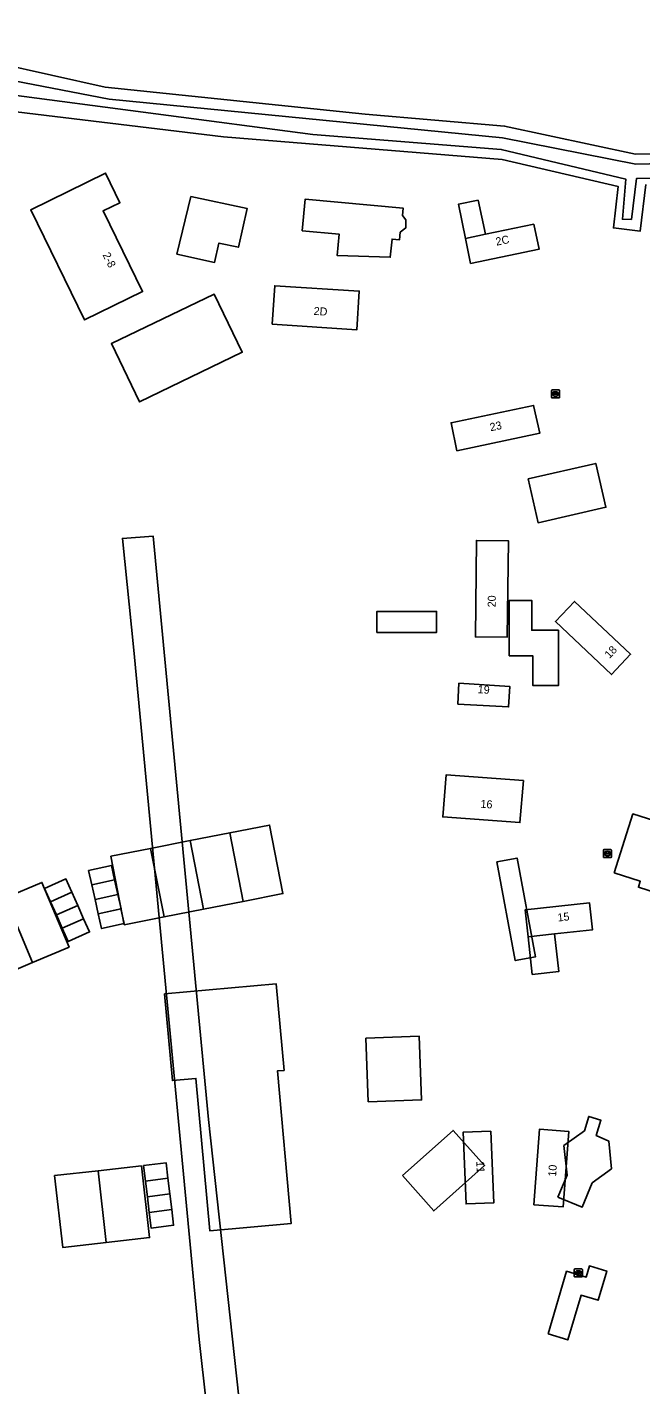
# Model space of a CAD drawing. Extents: x 159451 to 160664, y 388402 to 389723.
# Drawn here: x 160017.1 to 160093.8, y 389378.7 to 389548.3 of the extents above; entities that cross this region are included whole.
import ezdxf

# ---------------------------------------------------------------- set-up
doc = ezdxf.new("R2010")
doc.units = 0
for name, color, linetype in [('IMGEO_Groenvoorziening', 7, 'Continuous'), ('IMGEO_Oever', 7, 'Continuous'), ('IMGEO_Pand', 7, 'Continuous'), ('IMGEO_Pand_nummerreeks', 7, 'Continuous'), ('IMGEO_Pand_overbouw', 7, 'Continuous'), ('IMGEO_Pand_vergunning_verleend', 7, 'Continuous'), ('IMGEO_Rioolput', 7, 'Continuous'), ('IMGEO_Voetpad_open', 7, 'Continuous'), ('IMGEO_Waterloop', 7, 'Continuous')]:
    doc.layers.add(name, color=color, linetype=linetype)

msp = doc.modelspace()

# ---------------------------------------------------------------- linework, layer by layer
at = {"layer": 'IMGEO_Groenvoorziening'}
for points in [[(159864.26, 389539.27), (159877.37, 389542.72), (159910.67, 389547.35), (159921.89, 389548.25), (159950.46, 389547.42), (159979.98, 389545.51), (159991.18, 389543.87), (160013.37, 389543.74), (160026.85, 389540.77), (160059.3, 389537.37), (160076.74, 389535.9), (160093.1, 389532.4), (160106.88, 389532.52)], [(160094.37, 389528.6), (160093.68, 389522.77), (160090.33, 389523.17), (160090.94, 389528.33), (160076.45, 389531.72), (160041.63, 389534.55), (160012.22, 389538.08), (159935.54, 389544.19), (159921.34, 389544.14), (159894.12, 389541.21), (159881.2, 389539.62), (159858.79, 389532.6), (159882.61, 389518.89), (159882.88, 389518.48), (159883.08, 389518.04), (159883.14, 389517.69), (159883.16, 389517.57), (159883.13, 389517.08), (159883.07, 389516.85), (159882.73, 389516.23), (159882.42, 389515.86), (159882.06, 389515.52), (159881.7, 389515.21), (159821.76, 389475.8)], [(160039.49, 389376.11), (160038.58, 389384.31), (160030.41, 389470.42), (160029, 389484.38), (160032.85, 389484.66), (160039.74, 389411.81), (160043.52, 389377.12)]]:
    msp.add_lwpolyline(points, dxfattribs=at)
for points in [[(160031.52, 389515.23), (160024.27, 389511.69), (160017.55, 389525.44), (160026.88, 389530.02), (160028.69, 389526.32), (160026.58, 389525.29)], [(160072.49, 389518.74), (160071.85, 389521.86), (160074.34, 389522.38), (160080.37, 389523.63), (160081.04, 389520.52)], [(160031.13, 389501.44), (160027.61, 389508.73), (160040.45, 389514.92), (160043.96, 389507.64)], [(160058.28, 389510.46), (160047.72, 389511.16), (160048.03, 389515.95), (160058.57, 389515.28)], [(160081.12, 389497.53), (160070.78, 389495.34), (160070.05, 389498.84), (160080.36, 389501)], [(160077.05, 389472.05), (160073.08, 389472.08), (160073.22, 389484.14), (160077.21, 389484.09)], [(160092.47, 389469.92), (160090.07, 389467.39), (160083.08, 389474.01), (160085.45, 389476.52)], [(160077.24, 389463.34), (160070.91, 389463.7), (160071.03, 389466.3), (160077.41, 389465.88)], [(160079.09, 389454.17), (160078.65, 389448.89), (160069, 389449.6), (160069.44, 389454.87)], [(160087.7, 389435.49), (160082.99, 389434.98), (160079.68, 389434.62), (160079.31, 389438), (160087.34, 389438.88)], [(160075.38, 389401.38), (160071.92, 389401.26), (160071.54, 389410.21), (160075, 389410.33)], [(160084.06, 389400.9), (160080.4, 389401.16), (160081.08, 389410.59), (160084.74, 389410.32)]]:
    msp.add_lwpolyline(points, close=True, dxfattribs=at)
at = {"layer": 'IMGEO_Oever'}
for points in [[(159854.53, 389534.2), (159877.32, 389541.54), (159921.96, 389546.95), (159944.13, 389546.06), (159991.21, 389542.62), (160013.05, 389542.02), (160027.34, 389539.24), (160076.46, 389534.42), (160093.15, 389531.13), (160106.86, 389531.48)], [(160106.88, 389532.52), (160093.1, 389532.4), (160076.74, 389535.9), (160059.3, 389537.37), (160026.85, 389540.77), (160013.37, 389543.74), (159991.18, 389543.87), (159979.98, 389545.51), (159950.46, 389547.42), (159921.89, 389548.25), (159910.67, 389547.35), (159877.37, 389542.72), (159864.26, 389539.27)], [(160101.81, 389529.55), (160093.23, 389529.36), (160092.58, 389524.23), (160091.46, 389524.26), (160091.88, 389529.28), (160076.32, 389532.99), (160052.78, 389534.86), (160013.5, 389540), (159921.84, 389545.35), (159881.02, 389540.75), (159867.27, 389536.87)], [(159821.76, 389475.8), (159881.7, 389515.21), (159882.06, 389515.52), (159882.42, 389515.86), (159882.73, 389516.23), (159883.07, 389516.85), (159883.13, 389517.08), (159883.16, 389517.57), (159883.14, 389517.69), (159883.08, 389518.04), (159882.88, 389518.48), (159882.61, 389518.89), (159858.79, 389532.6), (159881.2, 389539.62), (159894.12, 389541.21), (159921.34, 389544.14), (159935.54, 389544.19), (160012.22, 389538.08), (160041.63, 389534.55), (160076.45, 389531.72), (160090.94, 389528.33), (160090.33, 389523.17), (160093.68, 389522.77), (160094.37, 389528.6)]]:
    msp.add_lwpolyline(points, dxfattribs=at)
at = {"layer": 'IMGEO_Pand'}
for points in [[(160026.58, 389525.29), (160028.69, 389526.32), (160026.88, 389530.02), (160017.55, 389525.44), (160024.27, 389511.69), (160031.52, 389515.23)], [(160080.37, 389523.63), (160074.34, 389522.38), (160071.85, 389521.86), (160072.49, 389518.74), (160081.04, 389520.52)], [(160043.96, 389507.64), (160040.45, 389514.92), (160027.61, 389508.73), (160031.13, 389501.44)], [(160058.57, 389515.28), (160048.03, 389515.95), (160047.72, 389511.16), (160058.28, 389510.46)], [(160080.36, 389501), (160070.05, 389498.84), (160070.78, 389495.34), (160081.12, 389497.53)], [(160077.21, 389484.09), (160073.22, 389484.14), (160073.08, 389472.08), (160077.05, 389472.05)], [(160085.45, 389476.52), (160083.08, 389474.01), (160090.07, 389467.39), (160092.47, 389469.92)], [(160077.41, 389465.88), (160071.03, 389466.3), (160070.91, 389463.7), (160077.24, 389463.34)], [(160079.09, 389454.17), (160069.44, 389454.87), (160069, 389449.6), (160078.65, 389448.89)], [(160079.31, 389438), (160079.68, 389434.62), (160082.99, 389434.98), (160087.7, 389435.49), (160087.34, 389438.88)], [(160071.92, 389401.26), (160075.38, 389401.38), (160075, 389410.33), (160071.54, 389410.21)], [(160084.74, 389410.32), (160081.08, 389410.59), (160080.4, 389401.16), (160084.06, 389400.9)]]:
    msp.add_lwpolyline(points, close=True, dxfattribs=at)
at = {"layer": 'IMGEO_Pand_overbouw'}
for points in [[(160073.45, 389526.66), (160070.97, 389526.14), (160071.85, 389521.86), (160074.34, 389522.38)], [(160079.68, 389434.62), (160080.2, 389429.92), (160083.51, 389430.28), (160082.99, 389434.98)]]:
    msp.add_lwpolyline(points, close=True, dxfattribs=at)
at = {"layer": 'IMGEO_Pand_vergunning_verleend'}
for points in [[(160035.81, 389519.91), (160037.54, 389527.09), (160044.57, 389525.62), (160043.48, 389520.75), (160041.05, 389521.29), (160040.51, 389518.86)], [(160051.45, 389522.81), (160051.81, 389526.76), (160064.05, 389525.66), (160063.99, 389524.72), (160064.4, 389524.18), (160064.38, 389523.18), (160063.71, 389522.64), (160063.62, 389521.7), (160062.68, 389521.79), (160062.46, 389519.51), (160055.84, 389519.71), (160056.08, 389522.38)], [(160079.66, 389491.82), (160088.13, 389493.75), (160089.39, 389488.28), (160080.91, 389486.34)], [(160077.31, 389469.71), (160077.31, 389476.64), (160080.12, 389476.64), (160080.12, 389472.92), (160083.45, 389472.92), (160083.45, 389466.01), (160080.27, 389466.01), (160080.27, 389469.71)], [(160060.77, 389472.65), (160060.77, 389475.25), (160068.23, 389475.27), (160068.23, 389472.65)], [(160042.42, 389447.61), (160047.37, 389448.58), (160049.05, 389440.02), (160044.09, 389439.05)], [(160090.42, 389442.62), (160092.77, 389449.97), (160096.42, 389448.81), (160095.16, 389444.87), (160098.43, 389443.83), (160097.09, 389439.64), (160093.45, 389440.81), (160093.69, 389441.57)], [(160032.51, 389445.67), (160037.46, 389446.64), (160039.14, 389438.08), (160034.19, 389437.11)], [(160037.46, 389446.64), (160042.42, 389447.61), (160044.09, 389439.05), (160039.14, 389438.08)], [(160027.56, 389444.7), (160032.51, 389445.67), (160034.19, 389437.11), (160029.23, 389436.14)], [(160024.76, 389442.91), (160027.61, 389443.55), (160028.01, 389441.74), (160025.17, 389441.1)], [(160075.76, 389443.98), (160078.3, 389444.45), (160080.6, 389432.13), (160078.06, 389431.66)], [(160019.27, 389440.66), (160021.93, 389441.85), (160022.67, 389440.2), (160020, 389439.01)], [(160025.17, 389441.1), (160028.01, 389441.74), (160028.42, 389439.93), (160025.58, 389439.29)], [(160014.38, 389439.49), (160018.94, 389441.42), (160022.34, 389433.35), (160017.78, 389431.43)], [(160020, 389439), (160022.67, 389440.2), (160023.41, 389438.54), (160020.74, 389437.35)], [(160025.58, 389439.29), (160028.42, 389439.93), (160028.83, 389438.11), (160025.98, 389437.48)], [(160009.46, 389437.41), (160014.38, 389439.49), (160017.78, 389431.43), (160012.86, 389429.35)], [(160020.74, 389437.35), (160023.41, 389438.54), (160024.15, 389436.89), (160021.48, 389435.69)], [(160025.98, 389437.48), (160028.79, 389438.11), (160029.2, 389436.29), (160026.39, 389435.66)], [(160021.48, 389435.69), (160024.15, 389436.89), (160024.89, 389435.23), (160022.22, 389434.04)], [(160034.25, 389427.5), (160048.19, 389428.77), (160049.18, 389417.94), (160048.35, 389417.87), (160050.09, 389398.82), (160039.93, 389397.89), (160038.18, 389416.94), (160035.24, 389416.67)], [(160059.42, 389421.97), (160066.08, 389422.21), (160066.36, 389414.25), (160059.7, 389414.02)], [(160083.38, 389402.1), (160084.57, 389404.86), (160084.15, 389408.54), (160086.71, 389410.41), (160087.25, 389412.18), (160088.76, 389411.72), (160088.18, 389409.8), (160089.75, 389409.11), (160090.07, 389405.65), (160087.66, 389403.89), (160086.42, 389400.85)], [(160063.97, 389404.79), (160070.3, 389410.44), (160074.23, 389406.04), (160067.89, 389400.39)], [(160025.95, 389405.4), (160031.37, 389406.01), (160032.38, 389397.05), (160026.95, 389396.44)], [(160031.63, 389406.07), (160034.45, 389406.41), (160034.68, 389404.46), (160031.87, 389404.12)], [(160020.52, 389404.79), (160025.95, 389405.4), (160026.95, 389396.44), (160021.53, 389395.83)], [(160031.87, 389404.12), (160034.68, 389404.46), (160034.92, 389402.5), (160032.11, 389402.16)], [(160032.11, 389402.16), (160034.92, 389402.5), (160035.16, 389400.55), (160032.34, 389400.2)], [(160032.34, 389400.2), (160035.16, 389400.55), (160035.39, 389398.59), (160032.58, 389398.25)], [(160082.16, 389385.02), (160084.48, 389392.85), (160086.93, 389392.13), (160087.34, 389393.51), (160089.5, 389392.87), (160088.42, 389389.23), (160086.29, 389389.86), (160084.63, 389384.28)]]:
    msp.add_lwpolyline(points, close=True, dxfattribs=at)
at = {"layer": 'IMGEO_Rioolput'}
for p, q in [((160082.59, 389502.02), (160082.59, 389502.87)), ((160082.67, 389502.94), (160083.52, 389502.94)), ((160083.08, 389502.72), (160083.11, 389502.72)), ((160083.59, 389502.87), (160083.59, 389502.02)), ((160083.52, 389501.94), (160082.67, 389501.94)), ((160082.85, 389502.44), (160082.85, 389502.45)), ((160082.89, 389502.49), (160083.29, 389502.49)), ((160083.29, 389502.4), (160082.89, 389502.4)), ((160083.1, 389502.16), (160083.08, 389502.16)), ((160083.34, 389502.45), (160083.34, 389502.44)), ((160089.09, 389444.6), (160089.09, 389445.45)), ((160089.16, 389445.53), (160090.01, 389445.53)), ((160089.34, 389445.02), (160089.34, 389445.03)), ((160089.78, 389444.98), (160089.38, 389444.98)), ((160089.39, 389445.07), (160089.79, 389445.07)), ((160089.57, 389445.31), (160089.6, 389445.31)), ((160089.83, 389445.03), (160089.83, 389445.02)), ((160090.09, 389445.45), (160090.09, 389444.6)), ((160090.01, 389444.53), (160089.16, 389444.53)), ((160089.6, 389444.75), (160089.57, 389444.75)), ((160085.44, 389392.21), (160085.44, 389393.06)), ((160085.52, 389393.14), (160086.37, 389393.14)), ((160085.7, 389392.63), (160085.7, 389392.64)), ((160086.14, 389392.59), (160085.74, 389392.59)), ((160085.75, 389392.68), (160086.14, 389392.68)), ((160085.93, 389392.92), (160085.96, 389392.92)), ((160085.95, 389392.36), (160085.93, 389392.36)), ((160086.19, 389392.64), (160086.19, 389392.63)), ((160086.45, 389393.06), (160086.45, 389392.21)), ((160086.37, 389392.14), (160085.52, 389392.14))]:
    msp.add_line(p, q, dxfattribs=at)
for points in [[(160082.59, 389502.02), (160082.59, 389502.87)], [(160082.67, 389502.94), (160083.52, 389502.94)], [(160083.59, 389502.87), (160083.59, 389502.02)], [(160083.52, 389501.94), (160082.67, 389501.94)], [(160089.09, 389444.6), (160089.09, 389445.45)], [(160089.16, 389445.53), (160090.01, 389445.53)], [(160090.09, 389445.45), (160090.09, 389444.6)], [(160090.01, 389444.53), (160089.16, 389444.53)], [(160085.44, 389392.21), (160085.44, 389393.06)], [(160085.52, 389393.14), (160086.37, 389393.14)], [(160086.45, 389393.06), (160086.45, 389392.21)], [(160086.37, 389392.14), (160085.52, 389392.14)]]:
    msp.add_lwpolyline(points, dxfattribs=at)
for centre, radius, start, end in [((160082.67, 389502.87), 0.0765, 91.552, 178.448), ((160082.67, 389502.87), 0.0765, 91.552, 178.448), ((160083.52, 389502.87), 0.0765, 1.552, 88.448), ((160083.52, 389502.87), 0.0765, 1.552, 88.448), ((160082.67, 389502.02), 0.0765, 181.552, 268.448), ((160082.67, 389502.02), 0.0765, 181.552, 268.448), ((160082.89, 389502.45), 0.0403, 85.8775, 175.7526), ((160082.89, 389502.44), 0.0366, 178.938, 274.7102), ((160083.3, 389502.45), 0.0386, 1.7309, 96.639), ((160083.29, 389502.44), 0.043, 264.8664, 352.4533), ((160083.52, 389502.02), 0.0765, 271.552, 358.448), ((160083.52, 389502.02), 0.0765, 271.552, 358.448), ((160089.16, 389445.45), 0.0765, 91.552, 178.448), ((160089.16, 389445.45), 0.0765, 91.552, 178.448), ((160089.39, 389445.03), 0.0403, 85.8775, 175.7526), ((160089.38, 389445.02), 0.0366, 178.938, 274.7102), ((160089.79, 389445.03), 0.043, 264.8664, 352.4533), ((160089.79, 389445.03), 0.0386, 1.7309, 96.639), ((160090.01, 389445.45), 0.0765, 1.552, 88.448), ((160090.01, 389445.45), 0.0765, 1.552, 88.448), ((160089.16, 389444.6), 0.0765, 181.552, 268.448), ((160089.16, 389444.6), 0.0765, 181.552, 268.448), ((160090.01, 389444.6), 0.0765, 271.552, 358.448), ((160090.01, 389444.6), 0.0765, 271.552, 358.448), ((160085.52, 389393.06), 0.0765, 91.552, 178.448), ((160085.52, 389393.06), 0.0765, 91.552, 178.448), ((160085.74, 389392.64), 0.0403, 85.8775, 175.7526), ((160085.74, 389392.63), 0.0366, 178.938, 274.7102), ((160086.15, 389392.64), 0.0386, 1.7309, 96.639), ((160086.14, 389392.64), 0.043, 264.8664, 352.4533), ((160086.37, 389393.06), 0.0765, 1.552, 88.448), ((160086.37, 389393.06), 0.0765, 1.552, 88.448), ((160085.52, 389392.21), 0.0765, 181.552, 268.448), ((160085.52, 389392.21), 0.0765, 181.552, 268.448), ((160086.37, 389392.21), 0.0765, 271.552, 358.448), ((160086.37, 389392.21), 0.0765, 271.552, 358.448)]:
    msp.add_arc(centre, radius, start, end, dxfattribs=at)
for centre, major_axis, ratio, start_param, end_param in [((160083.08, 389502.44), (-0.387, 0.002), 0.722429, 4.712389, 7.853982), ((160083.1, 389502.44), (-0.39, 0.002), 0.717154, 1.570796, 4.712389), ((160089.57, 389445.03), (-0.387, 0.002), 0.722429, 4.712389, 7.853982), ((160089.6, 389445.03), (-0.39, 0.002), 0.717154, 1.570796, 4.712389), ((160085.93, 389392.64), (-0.387, 0.002), 0.722429, 4.712389, 7.853982), ((160085.96, 389392.64), (-0.39, 0.002), 0.717154, 1.570796, 4.712389)]:
    msp.add_ellipse(centre, major_axis=major_axis, ratio=ratio, start_param=start_param, end_param=end_param, dxfattribs=at)
at = {"layer": 'IMGEO_Voetpad_open'}
msp.add_lwpolyline([(160039.74, 389411.81), (160032.85, 389484.66), (160029, 389484.38), (160030.41, 389470.42), (160038.58, 389384.31), (160039.49, 389376.11), (160039.62, 389374.92), (160037.55, 389374.64), (160038.03, 389371.1), (160036.04, 389370.93), (160036.17, 389368.93), (160036.11, 389368.42), (160046.19, 389370.47), (160045.93, 389372.32), (160045.57, 389377.18), (160043.52, 389377.12)], close=True, dxfattribs=at)
at = {"layer": 'IMGEO_Waterloop'}
for points in [[(160106.86, 389531.48), (160093.15, 389531.13), (160076.46, 389534.42), (160027.34, 389539.24), (160013.05, 389542.02), (159991.21, 389542.62), (159944.13, 389546.06), (159921.96, 389546.95), (159877.32, 389541.54), (159854.53, 389534.2)], [(159867.27, 389536.87), (159881.02, 389540.75), (159921.84, 389545.35), (160013.5, 389540), (160052.78, 389534.86), (160076.32, 389532.99), (160091.88, 389529.28), (160091.46, 389524.26), (160092.58, 389524.23), (160093.23, 389529.36), (160101.81, 389529.55)]]:
    msp.add_lwpolyline(points, dxfattribs=at)

# ---------------------------------------------------------------- texts
at = {"layer": 'IMGEO_Pand_nummerreeks'}
for s, rotation, p in [('2C', 11.7514, (160075.73, 389520.95)), ('2-8', 296.1209, (160026.48, 389519.83)), ('2D', 356.2013, (160052.86, 389512.32)), ('23', 11.9347, (160075, 389497.77)), ('20', 89.3356, (160075.62, 389475.78)), ('18', 46.6044, (160089.84, 389469.32)), ('19', 356.7456, (160073.36, 389465.06)), ('16', 355.7544, (160073.7, 389450.76)), ('15', 6.2624, (160083.4, 389436.53)), ('11', 272.4635, (160073.2, 389406.59)), ('10', 85.9036, (160083.16, 389404.64))]:
    msp.add_text(s, height=1, rotation=rotation, dxfattribs=at).set_placement(p)

doc.saveas('drawing.dxf')
